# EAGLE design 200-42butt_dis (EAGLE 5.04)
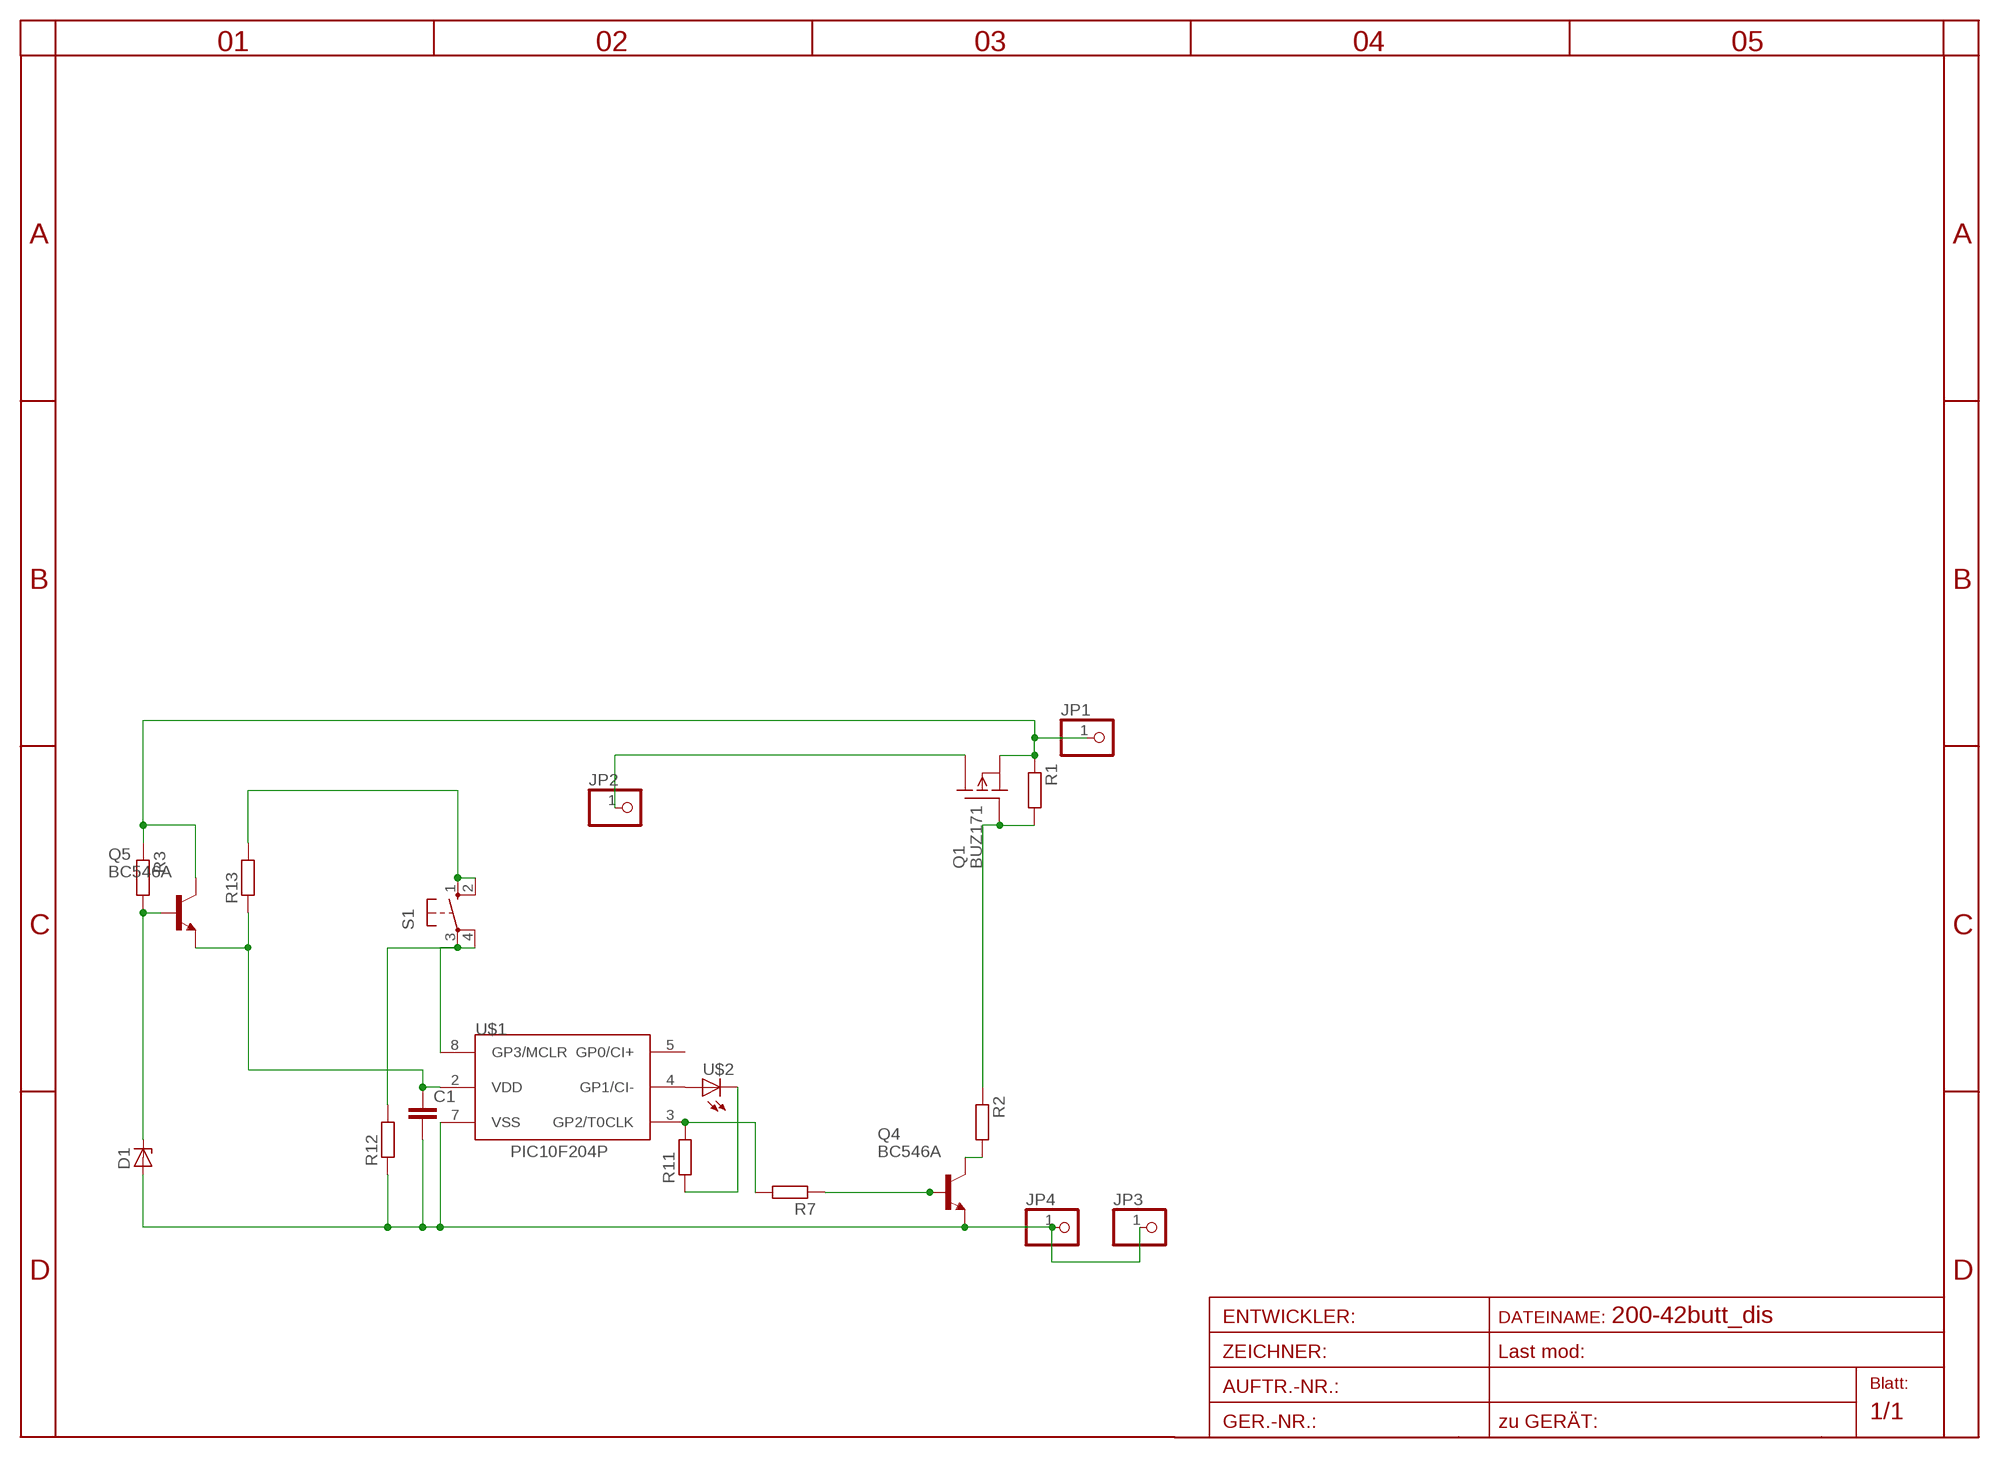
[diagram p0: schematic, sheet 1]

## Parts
C1  C-EU050-024X044  [C050-024X044]
D1  ZENER-DIODEZD-2.5  [ZDIO-2.5]
JP1  PINHD-1X1  [1X01]
JP2  PINHD-1X1  [1X01]
JP3  PINHD-1X1  [1X01]
JP4  PINHD-1X1  [1X01]
Q1  BUZ171  [TO220]
Q4  BC546A  [TO92-EBC]
Q5  BC546A  [TO92-EBC]
R1  R-EU_0204/2V  [0204V]
R2  R-EU_0204/2V  [0204V]
R3  R-EU_0204/2V  [0204V]
R7  R-EU_0204/2V  [0204V]
R11  R-EU_0204/2V  [0204V]
R12  R-EU_0204/2V  [0204V]
R13  R-EU_0204/2V  [0204V]
S1  10-XX  [B3F-10XX]
U$1  PIC10F204P  [DIL8]
U$2  LED3MM  [LED3MM]

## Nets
GND: C1.2 D1.A JP3.1 JP4.1 Q4.E R12.1 U$1.7(VSS)
N$2: C1.1 Q5.E R13.1 U$1.2(VDD)
N$3: Q4.C R2.2
N$4: D1.C Q5.B R3.2
N$5: U$1.4(GP1/CI-) U$2.A
N$6: R11.1 U$2.K(C)
N$7: Q1.1(G) R1.2 R2.1
N$9: R7.2 R11.2 U$1.3(GP2/T0CLK)
N$10: Q4.B R7.1
N$11: R12.2 S1.3(P) S1.4(P1) U$1.8(GP3/MCLR)
N$15: R13.2 S1.1(S) S1.2(S1)
V+IN: JP1.1 Q1.3(S) Q5.C R1.1 R3.1
V+OUT: JP2.1 Q1.2(D)
Unconnected: U$1.5(GP0/CI+)

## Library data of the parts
C1 = rcl:C-EU: CAPACITOR, European symbol
D1 = diode-1:ZENER-DIODE: Z-Diode
JP1-JP4 = pinhead:PINHD-1X1: PIN HEADER
Q1 = transistor-fet:BUZ171: P-Channel Enhancement MOSFET -50V; 7A; 0,4Ohm
Q4 Q5 = transistor-npn:BC546*: NPN Transistor
R1-R3 R7 R11-R13 = rcl:R-EU_: RESISTOR, European symbol
S1 = switch-omron:10-XX: OMRON SWITCH
U$1 = microchip-5:PIC10F2*: uPC nW 0,25/0,5k Program Flash memory Comparator
U$2 = led(2):LED: LED

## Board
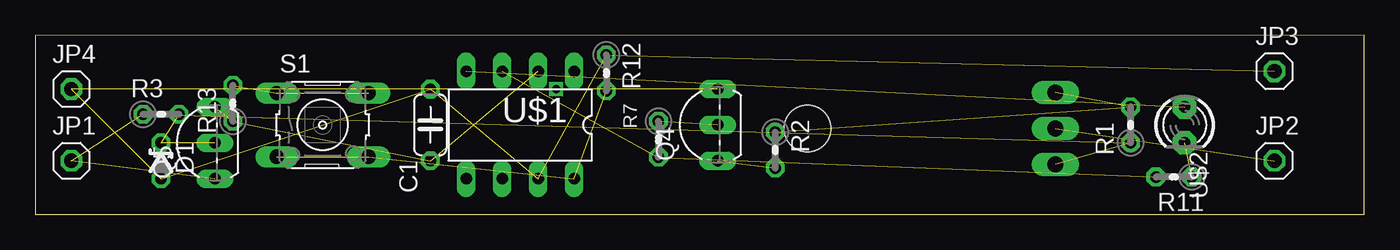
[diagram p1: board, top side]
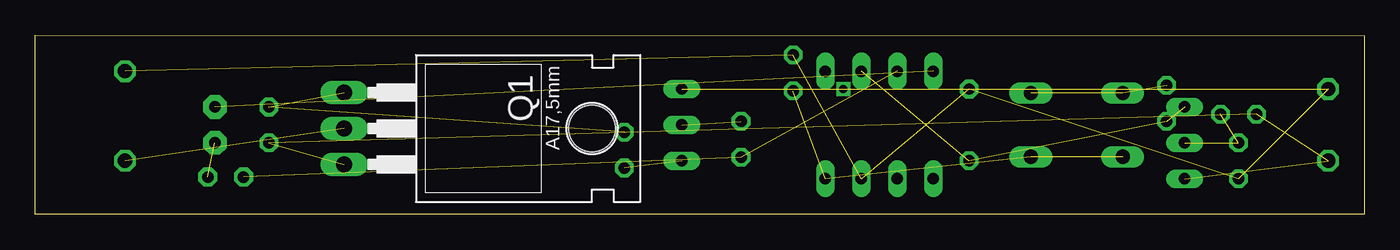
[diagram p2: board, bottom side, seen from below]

Size 93.98 x 12.7 mm. Coordinates in mm from the lower left corner, seen from the top.
Outline: 0,0 93.98,0 93.98,12.7 0,12.69 0,0
Copper layers (1*16): Top 0.035mm / dielectric 1.5mm / Bottom 0.035mm
Design rules "default": minimum track width 10mil, minimum drill 24mil, track to track 8mil, track to pad 8mil, pad to pad 8mil, via to via 8mil, smd to smd 8mil, copper to edge 40mil, drill to drill 8mil, minimum pad ring 10mil, minimum via ring 8mil, stop-mask expansion 4mil, vias tented up to drill 0mil, thermal gap 10mil

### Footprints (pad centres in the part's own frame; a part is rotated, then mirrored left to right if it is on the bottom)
C050-024X044 = drill 0.813 octagon: 1 -2.54,0; 2 2.54,0
ZDIO-2.5 = drill 0.813 octagon: A 1.27,0; C -1.27,0
1X01 = drill 1.016 octagon: 1 0,0
TO220 = drill 1.118 long: 1 -2.54,-6.35; 2 0,-6.35; 3 2.54,-6.35 | hole 3.302: 0,11.176
TO92-EBC = drill 0.813 long: B 0,-1.27; C -2.54,-1.27; E 2.54,-1.27
0204V = drill 0.813 octagon: 1 -1.27,0; 2 1.27,0
B3F-10XX = drill 1.016 long: 1 -3.251,2.261; 2 3.251,2.261; 3 -3.251,-2.261; 4 3.251,-2.261
DIL8 = drill 0.813 long: 1 -3.81,-3.81; 2 -1.27,-3.81; 3 1.27,-3.81; 4 3.81,-3.81; 5 3.81,3.81; 6 1.27,3.81; 7 -1.27,3.81; 8 -3.81,3.81
LED3MM = drill 0.813 pad 1.676 octagon: A -1.27,0; K 1.27,0

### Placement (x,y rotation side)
C1  27.94,6.35 90 top
D1  8.89,3.81 270 top
JP1  2.54,3.81 0 top
JP2  87.63,3.81 0 top
JP3  87.63,10.16 0 top
JP4  2.54,8.89 0 top
Q1  65.79,6.1 270 bottom
Q4  46.99,6.35 90 top
Q5  11.43,5.08 90 top
R1  77.47,6.35 90 top
R2  52.32,4.57 270 top
R3  8.89,7.11 0 top
R7  44.07,5.33 270 top
R11  80.52,2.67 180 top
R12  40.39,10.03 270 top
R13  13.97,7.87 90 top
S1  20.32,6.35 0 top
U$1  34.29,6.35 180 top
U$2  81.28,6.35 270 top

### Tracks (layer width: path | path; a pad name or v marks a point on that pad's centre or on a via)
GND  (6 unrouted)
N$1  (via drill 0.6)
  other vias: 36.83,8.89
N$2  (3 unrouted)
N$3  (1 unrouted)
N$4  (2 unrouted)
N$5  (1 unrouted)
N$6  (1 unrouted)
N$7  (2 unrouted)
N$9  (2 unrouted)
N$10  (1 unrouted)
N$11  (3 unrouted)
N$15  (2 unrouted)
V+IN  (4 unrouted)
V+OUT  (1 unrouted)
